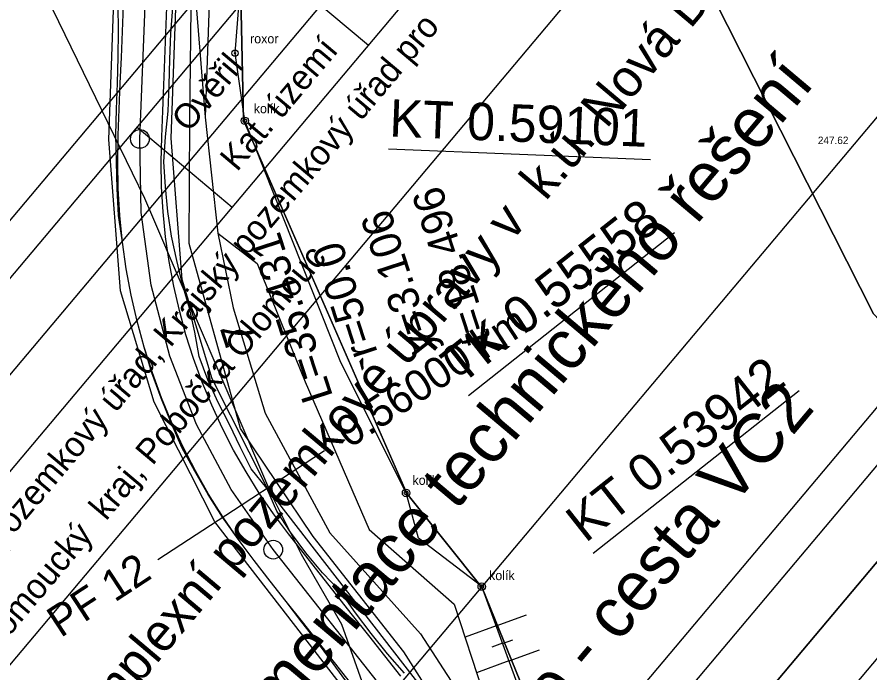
# Model space of a CAD drawing. Extents: x -555887 to -552101, y -1100251 to -1096546.
# Drawn here: x -554266 to -554197.5, y -1097056.9 to -1097004.2 of the extents above; entities that cross this region are included whole.
import ezdxf

# ---------------------------------------------------------------- set-up
doc = ezdxf.new("R2010")
doc.units = 0
for name, color, linetype in [('PARCELY_cesty', 7, 'Continuous'), ('PARCELY_VHO', 7, 'Continuous'), ('POLYGONY_SITUACE_PF', 7, 'Continuous'), ('POLYGONY_SITUACE_PF_POPISY', 7, 'Continuous'), ('POLYGONY_SITUACE_PO', 7, 'Continuous'), ('ram_VC2', 7, 'Continuous'), ('vrstevnice', 7, 'Continuous'), ('Výškopis', 7, 'Continuous'), ('ZSST', 7, 'Continuous'), ('zájem', 7, 'Continuous')]:
    doc.layers.add(name, color=color, linetype=linetype)

msp = doc.modelspace()

# ---------------------------------------------------------------- linework, layer by layer
for p, q in [((-554236.157, -1097014.792), (-554215.082, -1097015.639)), ((-554229.725, -1097034.59), (-554213.172, -1097021.518)), ((-554219.706, -1097047.278), (-554203.153, -1097034.206))]:
    msp.add_line(p, q)
at = {"layer": 'PARCELY_cesty'}
for points in [[(-554235.26, -1097250.21), (-554222.331, -1097095.103), (-554222.177, -1097088.532), (-554223.591, -1097078.803), (-554226.634, -1097069.372), (-554233.336, -1097058.257), (-554245.88, -1097042.059), (-554250.33, -1097033.26), (-554252.753, -1097025.27), (-554253.637, -1097013.936), (-554251.138, -1096944.546), (-554252.472, -1096936.15), (-554254.994, -1096928.042), (-554262.23, -1096914.12), (-554265.12, -1096907.97)], [(-554240.159, -1097243.281), (-554227.326, -1097094.829), (-554227.186, -1097088.835), (-554228.479, -1097079.938), (-554231.215, -1097071.458), (-554237.468, -1097061.088), (-554250.126, -1097044.743), (-554254.988, -1097035.128), (-554257.695, -1097026.201), (-554258.644, -1097014.04), (-554256.152, -1096944.852), (-554257.354, -1096937.291), (-554259.63, -1096929.971), (-554262.611, -1096924.345), (-554273.038, -1096923.935)]]:
    msp.add_lwpolyline(points, dxfattribs=at)
at = {"layer": 'PARCELY_VHO'}
for points in [[(-554130.46, -1097180.06), (-554159.17, -1097101.34), (-554159.64, -1097082.93), (-554163.72, -1097067.19), (-554173.74, -1097050.79), (-554190.63, -1097034.96), (-554197.16, -1097028.05), (-554217.46, -1096987.98), (-554225.33, -1096977.64), (-554234.21, -1096944.26), (-554236.99, -1096909.92), (-554235.22, -1096898.62), (-554228.6, -1096882.13), (-554225.73, -1096869.26), (-554224.9, -1096864.61), (-554220.11, -1096846.63), (-554200.4, -1096831.93), (-554179.17, -1096807.62), (-554142.08, -1096773.53), (-554110.69, -1096747.36), (-554089.18, -1096729.49)], [(-554235.26, -1097250.21), (-554222.331, -1097095.103), (-554222.177, -1097088.532), (-554223.591, -1097078.803), (-554226.634, -1097069.372), (-554233.336, -1097058.257), (-554245.88, -1097042.059), (-554250.33, -1097033.26), (-554252.753, -1097025.27), (-554253.637, -1097013.936), (-554251.138, -1096944.546), (-554252.472, -1096936.15), (-554254.994, -1096928.042), (-554262.23, -1096914.12), (-554265.12, -1096907.97), (-554264.18, -1096901.52), (-554256.593, -1096884.824), (-554225.08, -1096837.14), (-554208.2, -1096823.7)], [(-554200.4, -1096831.93), (-554220.11, -1096846.63), (-554224.9, -1096864.61), (-554233.29, -1096868.06), (-554243.42, -1096872.22), (-554247.48, -1096879.5), (-554255.66, -1096892.57), (-554260.45, -1096913.44), (-554248.68, -1096931.61), (-554247, -1096951.09), (-554248.74, -1096969.23), (-554247.82, -1097012.49), (-554234.69, -1097042.48), (-554228.63, -1097050.04), (-554218.79, -1097074.22), (-554216.52, -1097103.52), (-554219.47, -1097120.44), (-554219.42, -1097159.44)]]:
    msp.add_lwpolyline(points, dxfattribs=at)
at = {"layer": 'POLYGONY_SITUACE_PF'}
for p, q in [((-554248.003, -1097043.401), (-554241.311, -1097039.016)), ((-554254.694, -1097047.786), (-554248.003, -1097043.401))]:
    msp.add_line(p, q, dxfattribs=at)
at = {"layer": 'POLYGONY_SITUACE_PO'}
for p, q in [((-554256.141, -1097013.988), (-554253.571, -1096950.091)), ((-554257.847, -1097005.342), (-554257.893, -1097003.255)), ((-554257.545, -1097005.354), (-554257.461, -1097003.272)), ((-554257.545, -1097005.354), (-554257.461, -1097003.272)), ((-554254.048, -1097005.495), (-554253.964, -1097003.413)), ((-554254.048, -1097005.495), (-554253.964, -1097003.413)), ((-554253.64, -1097005.511), (-554253.491, -1097003.432)), ((-554257.889, -1097007.425), (-554257.847, -1097005.342)), ((-554257.629, -1097007.436), (-554257.545, -1097005.354)), ((-554257.629, -1097007.436), (-554257.545, -1097005.354)), ((-554254.132, -1097007.576), (-554254.048, -1097005.495)), ((-554254.132, -1097007.576), (-554254.048, -1097005.495)), ((-554253.727, -1097007.593), (-554253.64, -1097005.511)), ((-554257.948, -1097009.508), (-554257.889, -1097007.425)), ((-554257.712, -1097009.517), (-554257.629, -1097007.436)), ((-554257.712, -1097009.517), (-554257.629, -1097007.436)), ((-554254.215, -1097009.658), (-554254.132, -1097007.576)), ((-554254.215, -1097009.658), (-554254.132, -1097007.576)), ((-554253.787, -1097009.675), (-554253.727, -1097007.593)), ((-554258.011, -1097011.59), (-554257.948, -1097009.508)), ((-554257.796, -1097011.599), (-554257.712, -1097009.517)), ((-554257.796, -1097011.599), (-554257.712, -1097009.517)), ((-554254.299, -1097011.74), (-554254.215, -1097009.658)), ((-554254.299, -1097011.74), (-554254.215, -1097009.658)), ((-554253.871, -1097011.757), (-554253.787, -1097009.675)), ((-554258.075, -1097013.673), (-554258.011, -1097011.59)), ((-554257.88, -1097013.681), (-554257.796, -1097011.599)), ((-554257.88, -1097013.681), (-554257.796, -1097011.599)), ((-554254.383, -1097013.821), (-554254.299, -1097011.74)), ((-554254.383, -1097013.821), (-554254.299, -1097011.74)), ((-554254.083, -1097013.833), (-554253.871, -1097011.757)), ((-554258.019, -1097015.828), (-554258.075, -1097013.673)), ((-554257.923, -1097015.828), (-554257.88, -1097013.681)), ((-554257.923, -1097015.828), (-554257.88, -1097013.681)), ((-554256.03, -1097019.889), (-554256.141, -1097013.988)), ((-554254.423, -1097015.839), (-554254.383, -1097013.821)), ((-554254.423, -1097015.839), (-554254.383, -1097013.821)), ((-554254.22, -1097015.84), (-554254.083, -1097013.833)), ((-554257.962, -1097017.986), (-554258.019, -1097015.828)), ((-554257.887, -1097017.983), (-554257.923, -1097015.828)), ((-554257.887, -1097017.983), (-554257.923, -1097015.828)), ((-554254.39, -1097017.849), (-554254.423, -1097015.839)), ((-554254.39, -1097017.849), (-554254.423, -1097015.839)), ((-554254.092, -1097017.838), (-554254.22, -1097015.84)), ((-554257.847, -1097020.142), (-554257.962, -1097017.986)), ((-554257.76, -1097020.135), (-554257.887, -1097017.983)), ((-554257.76, -1097020.135), (-554257.887, -1097017.983)), ((-554254.271, -1097019.856), (-554254.39, -1097017.849)), ((-554254.271, -1097019.856), (-554254.39, -1097017.849)), ((-554253.881, -1097019.824), (-554254.092, -1097017.838)), ((-554257.543, -1097022.28), (-554257.847, -1097020.142)), ((-554257.543, -1097022.28), (-554257.76, -1097020.135)), ((-554257.543, -1097022.28), (-554257.76, -1097020.135)), ((-554255.224, -1097025.735), (-554256.03, -1097019.889)), ((-554254.069, -1097021.855), (-554254.271, -1097019.856)), ((-554254.069, -1097021.855), (-554254.271, -1097019.856)), ((-554253.601, -1097021.798), (-554253.881, -1097019.824)), ((-554253.175, -1097023.745), (-554253.601, -1097021.798)), ((-554257.234, -1097024.414), (-554257.543, -1097022.28)), ((-554257.543, -1097022.28), (-554257.543, -1097022.28)), ((-554257.234, -1097024.414), (-554257.543, -1097022.28)), ((-554257.234, -1097024.414), (-554257.543, -1097022.28)), ((-554253.781, -1097023.845), (-554254.069, -1097021.855)), ((-554253.781, -1097023.845), (-554254.069, -1097021.855)), ((-554253.414, -1097025.821), (-554253.781, -1097023.845)), ((-554253.414, -1097025.821), (-554253.781, -1097023.845)), ((-554252.71, -1097025.675), (-554253.175, -1097023.745)), ((-554256.84, -1097026.534), (-554257.234, -1097024.414)), ((-554256.84, -1097026.534), (-554257.234, -1097024.414)), ((-554256.84, -1097026.534), (-554257.234, -1097024.414)), ((-554253.735, -1097031.446), (-554255.224, -1097025.735)), ((-554252.966, -1097027.78), (-554253.414, -1097025.821)), ((-554252.966, -1097027.78), (-554253.414, -1097025.821)), ((-554252.146, -1097027.574), (-554252.71, -1097025.675)), ((-554256.365, -1097028.636), (-554256.84, -1097026.534)), ((-554256.84, -1097026.534), (-554256.84, -1097026.534)), ((-554256.36, -1097028.635), (-554256.84, -1097026.534)), ((-554256.36, -1097028.635), (-554256.84, -1097026.534)), ((-554252.435, -1097029.719), (-554252.966, -1097027.78)), ((-554252.435, -1097029.719), (-554252.966, -1097027.78)), ((-554251.712, -1097029.505), (-554252.146, -1097027.574)), ((-554255.796, -1097030.716), (-554256.365, -1097028.636)), ((-554255.79, -1097030.714), (-554256.36, -1097028.635)), ((-554255.79, -1097030.714), (-554256.36, -1097028.635)), ((-554251.824, -1097031.634), (-554252.435, -1097029.719)), ((-554251.824, -1097031.634), (-554252.435, -1097029.719)), ((-554251.37, -1097031.478), (-554251.712, -1097029.505)), ((-554255.178, -1097032.783), (-554255.796, -1097030.716)), ((-554255.135, -1097032.768), (-554255.79, -1097030.714)), ((-554255.135, -1097032.768), (-554255.79, -1097030.714)), ((-554251.583, -1097036.942), (-554253.735, -1097031.446)), ((-554251.131, -1097033.521), (-554251.824, -1097031.634)), ((-554251.131, -1097033.521), (-554251.824, -1097031.634)), ((-554250.665, -1097033.339), (-554251.37, -1097031.478)), ((-554254.432, -1097034.808), (-554255.178, -1097032.783)), ((-554254.392, -1097034.792), (-554255.135, -1097032.768)), ((-554254.392, -1097034.792), (-554255.135, -1097032.768)), ((-554249.851, -1097035.154), (-554250.665, -1097033.339)), ((-554250.365, -1097035.379), (-554251.131, -1097033.521)), ((-554250.365, -1097035.379), (-554251.131, -1097033.521)), ((-554253.619, -1097036.807), (-554254.432, -1097034.808)), ((-554253.57, -1097036.785), (-554254.392, -1097034.792)), ((-554253.57, -1097036.785), (-554254.392, -1097034.792)), ((-554249.521, -1097037.204), (-554250.365, -1097035.379)), ((-554249.521, -1097037.204), (-554250.365, -1097035.379)), ((-554248.947, -1097036.923), (-554249.851, -1097035.154)), ((-554252.757, -1097038.787), (-554253.619, -1097036.807)), ((-554252.665, -1097038.742), (-554253.57, -1097036.785)), ((-554252.665, -1097038.742), (-554253.57, -1097036.785)), ((-554248.799, -1097042.145), (-554251.583, -1097036.942)), ((-554248.601, -1097038.991), (-554249.521, -1097037.204)), ((-554248.601, -1097038.991), (-554249.521, -1097037.204)), ((-554248.086, -1097038.712), (-554248.947, -1097036.923)), ((-554251.735, -1097040.69), (-554252.757, -1097038.787)), ((-554251.678, -1097040.659), (-554252.665, -1097038.742)), ((-554251.678, -1097040.659), (-554252.665, -1097038.742)), ((-554247.2, -1097040.496), (-554248.086, -1097038.712)), ((-554247.608, -1097040.739), (-554248.601, -1097038.991)), ((-554247.608, -1097040.739), (-554248.601, -1097038.991)), ((-554250.66, -1097042.562), (-554251.735, -1097040.69)), ((-554250.613, -1097042.534), (-554251.678, -1097040.659)), ((-554250.613, -1097042.534), (-554251.678, -1097040.659)), ((-554246.539, -1097042.442), (-554247.608, -1097040.739)), ((-554246.539, -1097042.442), (-554247.608, -1097040.739)), ((-554245.926, -1097042.04), (-554247.2, -1097040.496)), ((-554245.421, -1097046.985), (-554248.799, -1097042.145)), ((-554245.122, -1097043.899), (-554245.926, -1097042.04)), ((-554249.498, -1097044.381), (-554250.66, -1097042.562)), ((-554249.467, -1097044.36), (-554250.613, -1097042.534)), ((-554249.467, -1097044.36), (-554250.613, -1097042.534)), ((-554245.4, -1097044.098), (-554246.539, -1097042.442)), ((-554245.4, -1097044.098), (-554246.539, -1097042.442)), ((-554248.248, -1097046.139), (-554249.498, -1097044.381)), ((-554248.246, -1097046.137), (-554249.467, -1097044.36)), ((-554248.246, -1097046.137), (-554249.467, -1097044.36)), ((-554244.196, -1097045.708), (-554245.4, -1097044.098)), ((-554244.196, -1097045.708), (-554245.4, -1097044.098)), ((-554244.037, -1097045.583), (-554245.122, -1097043.899)), ((-554242.913, -1097047.338), (-554244.196, -1097045.708)), ((-554242.913, -1097047.338), (-554244.196, -1097045.708)), ((-554242.79, -1097047.241), (-554244.037, -1097045.583)), ((-554246.954, -1097047.863), (-554248.248, -1097046.139)), ((-554246.954, -1097047.863), (-554248.246, -1097046.137)), ((-554246.954, -1097047.863), (-554248.246, -1097046.137)), ((-554235.402, -1097059.672), (-554245.421, -1097046.985)), ((-554245.66, -1097049.507), (-554246.954, -1097047.863)), ((-554246.954, -1097047.863), (-554246.954, -1097047.863)), ((-554245.66, -1097049.507), (-554246.954, -1097047.863)), ((-554245.66, -1097049.507), (-554246.954, -1097047.863)), ((-554241.622, -1097048.973), (-554242.913, -1097047.338)), ((-554241.622, -1097048.973), (-554242.913, -1097047.338)), ((-554241.459, -1097048.845), (-554242.79, -1097047.241)), ((-554240.33, -1097050.608), (-554241.622, -1097048.973)), ((-554240.33, -1097050.608), (-554241.622, -1097048.973)), ((-554240.003, -1097050.35), (-554241.459, -1097048.845)), ((-554244.388, -1097051.158), (-554245.66, -1097049.507)), ((-554245.66, -1097049.507), (-554245.66, -1097049.507)), ((-554244.368, -1097051.142), (-554245.66, -1097049.507)), ((-554244.368, -1097051.142), (-554245.66, -1097049.507)), ((-554239.039, -1097052.243), (-554240.33, -1097050.608)), ((-554239.039, -1097052.243), (-554240.33, -1097050.608)), ((-554238.807, -1097052.059), (-554240.003, -1097050.35)), ((-554243.133, -1097052.821), (-554244.388, -1097051.158)), ((-554243.077, -1097052.777), (-554244.368, -1097051.142)), ((-554243.077, -1097052.777), (-554244.368, -1097051.142)), ((-554237.748, -1097053.878), (-554239.039, -1097052.243)), ((-554237.748, -1097053.878), (-554239.039, -1097052.243)), ((-554237.542, -1097053.715), (-554238.807, -1097052.059)), ((-554241.827, -1097054.444), (-554243.133, -1097052.821)), ((-554241.786, -1097054.412), (-554243.077, -1097052.777)), ((-554241.786, -1097054.412), (-554243.077, -1097052.777)), ((-554236.457, -1097055.513), (-554237.748, -1097053.878)), ((-554236.457, -1097055.513), (-554237.748, -1097053.878)), ((-554236.239, -1097055.341), (-554237.542, -1097053.715)), ((-554240.598, -1097056.129), (-554241.827, -1097054.444)), ((-554240.495, -1097056.047), (-554241.786, -1097054.412)), ((-554240.495, -1097056.047), (-554241.786, -1097054.412)), ((-554234.86, -1097056.906), (-554236.239, -1097055.341)), ((-554239.204, -1097057.682), (-554240.495, -1097056.047)), ((-554239.204, -1097057.682), (-554240.495, -1097056.047)), ((-554235.166, -1097057.148), (-554236.457, -1097055.513)), ((-554235.166, -1097057.148), (-554236.457, -1097055.513)), ((-554239.365, -1097057.809), (-554240.598, -1097056.129))]:
    msp.add_line(p, q, dxfattribs=at)
for centre in [(-554256.141, -1097013.988), (-554245.421, -1097046.985)]:
    msp.add_circle(centre, 0.75, dxfattribs=at)
at = {"layer": 'ram_VC2'}
for p, q in [((-554279.698, -1097071.818), (-554163.803, -1096934.092)), ((-554260.569, -1097087.915), (-554144.674, -1096950.189)), ((-554291.175, -1097062.16), (-554213.912, -1096970.343)), ((-554287.349, -1097065.379), (-554210.086, -1096973.562)), ((-554245.423, -1097000.025), (-554237.772, -1097006.463)), ((-554256.369, -1097013.032), (-554248.717, -1097019.471))]:
    msp.add_line(p, q, dxfattribs=at)
for points in [[(-554114.88, -1096958.27), (-554342.128, -1096767.044), (-555018.181, -1097570.444), (-554790.933, -1097761.671)], [(-554121.925, -1096958.876), (-554341.521, -1096774.089), (-555011.135, -1097569.838), (-554791.539, -1097754.626)], [(-554299.227, -1097059.305), (-554179.469, -1096916.988), (-554128.97, -1096959.483), (-554248.728, -1097101.8)], [(-554295, -1097058.941), (-554179.106, -1096921.215), (-554133.197, -1096959.847), (-554249.092, -1097097.572)]]:
    msp.add_lwpolyline(points, close=True, dxfattribs=at)
for points in [[(-554114.88, -1096958.27), (-554342.128, -1096767.044), (-555018.181, -1097570.444), (-554790.933, -1097761.671), (-554114.88, -1096958.27)], [(-554791.539, -1097754.626), (-555011.135, -1097569.838), (-554341.521, -1096774.089), (-554121.925, -1096958.876), (-554791.539, -1097754.626)]]:
    msp.add_lwpolyline(points, dxfattribs=at)
at = {"layer": 'vrstevnice'}
msp.add_lwpolyline([(-554268.115, -1096993.424), (-554255.755, -1097018.757), (-554245.563, -1097042.574), (-554243.178, -1097047.337), (-554239.926, -1097052.967), (-554237.54, -1097059.679), (-554234.721, -1097068.34), (-554229.517, -1097084.578), (-554230.602, -1097094.322), (-554232.77, -1097101.25), (-554238.191, -1097103.849), (-554244.913, -1097103.416), (-554253.586, -1097099.518), (-554258.357, -1097095.404), (-554264.645, -1097088.043), (-554288.064, -1097053.616), (-554306.513, -1097026.61), (-554314.68, -1097013.265), (-554321.807, -1096999.772)], dxfattribs=at)
at = {"layer": 'ZSST'}
for p, q in [((-554230.87, -1097051.37), (-554226.53, -1097064.63)), ((-554227.501, -1097053.112), (-554225.06, -1097052.218)), ((-554227.505, -1097053.101), (-554230.004, -1097054.016)), ((-554226.989, -1097054.509), (-554227.837, -1097054.82)), ((-554226.985, -1097054.521), (-554226.172, -1097054.223)), ((-554226.468, -1097055.929), (-554224.028, -1097055.035)), ((-554226.473, -1097055.917), (-554229.07, -1097056.869))]:
    msp.add_line(p, q, dxfattribs=at)
for points in [[(-554252.3, -1096962.91), (-554252.15, -1096975.19), (-554251.67, -1096987.35), (-554251.95, -1096998.96), (-554250.9, -1097012.23), (-554249.88, -1097021.55), (-554248.64, -1097027.57), (-554246.07, -1097036.01), (-554240.86, -1097045.62), (-554233.57, -1097053.76), (-554226.53, -1097064.63), (-554223.28, -1097073.72), (-554220.82, -1097084.32), (-554219.54, -1097095.27), (-554223.32, -1097113.64)], [(-554218.54, -1097175.67), (-554218.88, -1097171.11), (-554218.23, -1097160.44), (-554219.16, -1097151.75), (-554218.79, -1097120.84), (-554218.38, -1097111.65), (-554216.83, -1097104.6), (-554216.54, -1097100.8), (-554217.26, -1097093.11), (-554218.21, -1097084.79), (-554219.72, -1097074.34), (-554228.66, -1097049.95), (-554233.75, -1097046.05), (-554234.74, -1097042.43), (-554239.98, -1097031.94), (-554247.7, -1097012.53), (-554248.49, -1097007.1), (-554246.97, -1096987.92), (-554248.9, -1096972.89), (-554248.75, -1096969.32)], [(-554252.15, -1096975.19), (-554249.63, -1096988.14), (-554250.42, -1096998.55), (-554250.9, -1097012.23)], [(-554223.32, -1097113.64), (-554221.4, -1097095.79), (-554222, -1097084.45), (-554224.47, -1097074.24), (-554228.76, -1097064.88), (-554234.93, -1097055.2), (-554242.22, -1097045.94), (-554248.05, -1097037.26), (-554252.18, -1097022.38), (-554252.13, -1097012.54), (-554251.95, -1096998.96)], [(-554249.88, -1097021.55), (-554246.7, -1097023.99), (-554242.84, -1097033.5), (-554237.72, -1097045.37), (-554230.87, -1097051.37)]]:
    msp.add_lwpolyline(points, dxfattribs=at)
for centre, radius in [((-554248.49, -1097007.1), 0.25), ((-554248.49, -1097007.1), 0.05), ((-554247.7, -1097012.53), 0.3), ((-554247.7, -1097012.53), 0.15), ((-554234.74, -1097042.43), 0.3), ((-554234.74, -1097042.43), 0.15), ((-554228.66, -1097049.95), 0.3), ((-554228.66, -1097049.95), 0.15)]:
    msp.add_circle(centre, radius, dxfattribs=at)
at = {"layer": 'zájem'}
for points in [[(-554248.74, -1096969.23), (-554247.82, -1097012.49), (-554234.69, -1097042.48), (-554228.63, -1097050.04), (-554218.79, -1097074.22), (-554216.52, -1097103.52), (-554219.47, -1097120.44), (-554219.42, -1097159.44)], [(-554219.42, -1097159.44), (-554219.47, -1097120.44), (-554216.52, -1097103.52), (-554218.79, -1097074.22), (-554228.63, -1097050.04), (-554234.69, -1097042.48), (-554247.82, -1097012.49), (-554248.74, -1096969.23)], [(-554130.46, -1097180.06), (-554159.17, -1097101.34), (-554159.64, -1097082.93), (-554163.72, -1097067.19), (-554173.74, -1097050.79), (-554190.63, -1097034.96), (-554197.16, -1097028.05), (-554217.46, -1096987.98)], [(-554217.46, -1096987.98), (-554197.16, -1097028.05), (-554190.63, -1097034.96), (-554173.74, -1097050.79), (-554163.72, -1097067.19), (-554159.64, -1097082.93), (-554159.17, -1097101.34), (-554130.46, -1097180.06)]]:
    msp.add_lwpolyline(points, dxfattribs=at)

# ---------------------------------------------------------------- texts
for s, height, rotation, p in [('KT 0.59101', 3, 357.69671, (-554236.117, -1097013.793)), ('t=18.496', 2.5, 107.99716, (-554227.896, -1097030.068)), ('TK 0.55558', 3, 38.29761, (-554230.345, -1097033.805)), ('y=3.106', 2.5, 107.99716, (-554232.36, -1097030.892)), ('L=35.431', 2.5, 107.99716, (-554240.593, -1097034.678)), ('r=50.0', 2.5, 107.99716, (-554237.009, -1097031.148)), ('7', 2.5, 107.99716, (-554246.786, -1097030.179)), ('KT 0.53942', 3, 38.29761, (-554220.326, -1097046.493))]:
    msp.add_text(s, height=height, rotation=rotation).set_placement(p)
at = {"layer": 'POLYGONY_SITUACE_PF_POPISY'}
for s, p in [('0.56000 km', (-554239.297, -1097038.892)), ('PF 12', (-554262.511, -1097054.103))]:
    msp.add_text(s, height=2.5, rotation=33.23472, dxfattribs=at).set_placement(p)
at = {"layer": 'ram_VC2'}
for s, height, p in [('Komplexní pozemkové úpravy v  k.ú. Nová Dědina u Uničova', 3, (-554261.566, -1097064.249)), ('Státní pozemkový úřad, Krajský pozemkový úřad pro', 2, (-554272.257, -1097052.881)), ('Kat. území', 2, (-554248.334, -1097016.686)), ('Dokumentace technického řešení', 4, (-554252.931, -1097070.296)), ('Ověřil', 2, (-554252.223, -1097013.541)), ('Olomoucký  kraj, Pobočka Olomouc', 2, (-554268.429, -1097056.098)), ('SO3 Situace - cesta VC2', 4, (-554240.078, -1097081.138))]:
    msp.add_text(s, height=height, rotation=49.91975, dxfattribs=at).set_placement(p)
at = {"layer": 'Výškopis'}
msp.add_text('247.62', height=0.6, dxfattribs=at).set_placement((-554201.639, -1097014.4))
at = {"layer": 'ZSST'}
for s, p in [('roxor', (-554247.283, -1097006.31)), ('kolík', (-554246.986, -1097011.924)), ('kolík', (-554234.228, -1097041.781)), ('kolík', (-554228.072, -1097049.432))]:
    msp.add_text(s, height=0.75, dxfattribs=at).set_placement(p)

doc.saveas('drawing.dxf')
